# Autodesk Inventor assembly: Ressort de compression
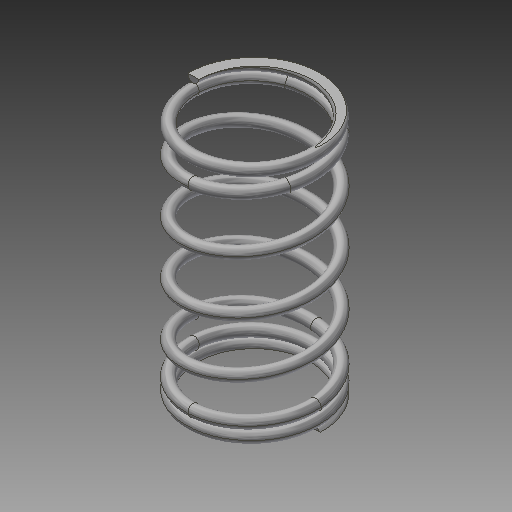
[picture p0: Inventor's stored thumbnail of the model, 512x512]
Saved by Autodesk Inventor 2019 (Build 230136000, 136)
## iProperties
Created: 2018-06
Part Number: Ressort de compression
Document SubType Name: Assembly
Designer: Fabian Perrée
ClientObjectVersion: 1
Author: Fabian Perrée
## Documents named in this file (2)
- C:\Users\Fabian\Google Drive\04_CAO\01_Inventor\Fichiers_exercice_Inventor\Definitif\Capteur\Capteur_V1\Design Accelerator\Ressort de compression1.iam
- C:\Users\Fabian\Google Drive\04_CAO\01_Inventor\Fichiers_exercice_Inventor\Definitif\Capteur\Capteur_V1\Design Accelerator\Ressort de compression11.ipt
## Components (1 placed, 1 different names)
1. Ressort de compression1:1
